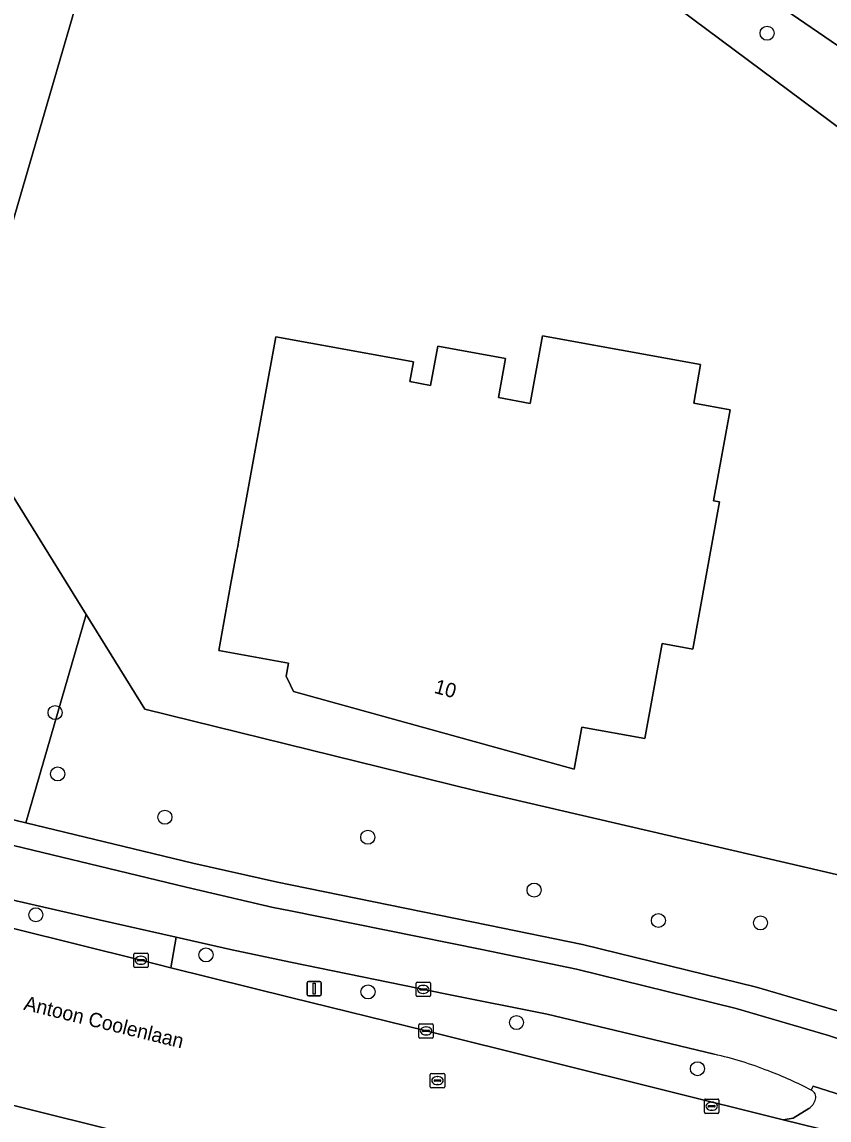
# Model space of a CAD drawing. Extents: x 159817 to 160765, y 380688 to 381638.
# Drawn here: x 160481.3 to 160537.5, y 380889.1 to 380965.5 of the extents above; entities that cross this region are included whole.
import ezdxf

# ---------------------------------------------------------------- set-up
doc = ezdxf.new("R2010")
doc.units = 0
for name, color, linetype in [('IMGEO_Berm_groen', 7, 'Continuous'), ('IMGEO_Boom', 7, 'Continuous'), ('IMGEO_Erf', 7, 'Continuous'), ('IMGEO_Fietspad_gesloten', 7, 'Continuous'), ('IMGEO_Gemengd_bos', 7, 'Continuous'), ('IMGEO_Grasland_overig', 7, 'Continuous'), ('IMGEO_Hek', 7, 'Continuous'), ('IMGEO_Kolk', 7, 'Continuous'), ('IMGEO_Lichtmast', 7, 'Continuous'), ('IMGEO_Openbare_ruimte_label', 7, 'Continuous'), ('IMGEO_Pand', 7, 'Continuous'), ('IMGEO_Pand_nummerreeks', 7, 'Continuous'), ('IMGEO_Rijbaan_lokaal_gesloten', 7, 'Continuous'), ('IMGEO_Rijbaan_lokaal_open', 7, 'Continuous'), ('IMGEO_Rioolput', 7, 'Continuous'), ('IMGEO_Verkeerseiland_gesloten', 7, 'Continuous'), ('IMGEO_Voetpad_gesloten', 7, 'Continuous'), ('IMGEO_Voetpad_open', 7, 'Continuous')]:
    doc.layers.add(name, color=color, linetype=linetype)

msp = doc.modelspace()

# ---------------------------------------------------------------- linework, layer by layer
at = {"layer": 'IMGEO_Berm_groen'}
for points in [[(160467.63, 380905.686), (160489.586, 380900.228), (160491.667, 380899.712), (160492.052, 380901.84), (160486.675, 380903.051), (160480.593, 380904.443)], [(160517.859, 380896.483), (160510.889, 380897.864), (160500, 380900.104), (160495.835, 380900.988), (160492.052, 380901.84), (160491.667, 380899.712), (160500, 380897.648), (160509.439, 380895.309), (160534.288, 380889.115), (160535.003, 380889.239), (160536.093, 380889.922)], [(160529.491, 380893.685), (160524.664, 380894.858), (160517.859, 380896.483)]]:
    msp.add_lwpolyline(points, dxfattribs=at)
for centre, radius, start, end in [((160524.069, 380869.182), 25.096, 68.45926, 77.52225), ((160524.458, 380869.13), 25.004, 61.86676, 69.33272), ((160535.56, 380890.771), 1.003, 302.13777, 347.91431), ((160536.055, 380890.71), 0.508, 342.8831, 67.62608)]:
    msp.add_arc(centre, radius, start, end, dxfattribs=at)
at = {"layer": 'IMGEO_Boom'}
for centre in [(160533.174, 380964.739), (160483.613, 380917.461), (160483.791, 380913.193), (160491.255, 380910.183), (160505.382, 380908.787), (160516.958, 380905.114), (160482.272, 380903.392), (160525.609, 380902.995), (160532.72, 380902.83), (160494.117, 380900.6), (160505.397, 380898.025), (160515.733, 380895.892), (160528.327, 380892.683)]:
    msp.add_circle(centre, 0.489, dxfattribs=at)
at = {"layer": 'IMGEO_Erf'}
for points in [[(160554.891, 380940.824), (160556.535, 380944.511), (160525.173, 380967.859), (160500, 380984.04), (160491.657, 380989.31), (160476.872, 380938.65), (160485.779, 380924.29), (160489.858, 380917.713), (160512.835, 380912.045), (160539.32, 380905.895)], [(160528.013, 380921.887), (160525.869, 380922.277), (160524.668, 380915.656), (160520.27, 380916.455), (160519.738, 380913.523), (160500.219, 380918.926), (160500, 380919.377), (160499.697, 380920.002), (160499.86, 380920.9), (160495.008, 380921.78), (160495.834, 380926.33), (160496.287, 380928.83), (160496.324, 380929.032), (160496.407, 380929.49), (160498.97, 380943.612), (160503.859, 380942.726), (160508.553, 380941.875), (160508.304, 380940.498), (160509.751, 380940.236), (160510.246, 380942.962), (160514.969, 380942.105), (160514.475, 380939.38), (160516.689, 380938.979), (160517.541, 380943.673), (160528.552, 380941.675), (160528.067, 380938.999), (160530.596, 380938.541), (160529.447, 380932.205), (160529.871, 380932.129)]]:
    msp.add_lwpolyline(points, close=True, dxfattribs=at)
at = {"layer": 'IMGEO_Fietspad_gesloten'}
for points in [[(160536.248, 380891.18), (160536.375, 380891.457), (160544.557, 380888.869), (160544.527, 380888.723), (160552.941, 380885.966), (160561.203, 380883.508), (160561.818, 380886.616), (160554.106, 380889.112), (160545.645, 380892.233), (160537.445, 380895.002), (160531.026, 380896.883), (160519.907, 380899.598), (160513.32, 380900.979), (160500, 380903.659), (160498.8, 380903.9), (160492.748, 380905.309), (160477.319, 380909.032)], [(160480.593, 380904.443), (160486.675, 380903.051), (160492.052, 380901.84), (160495.835, 380900.988), (160500, 380900.104), (160510.889, 380897.864), (160517.859, 380896.483), (160524.664, 380894.858), (160529.491, 380893.685)]]:
    msp.add_lwpolyline(points, dxfattribs=at)
for centre, radius, start, end in [((160524.069, 380869.182), 25.096, 68.45926, 77.52225), ((160524.458, 380869.13), 25.004, 61.86676, 69.33272)]:
    msp.add_arc(centre, radius, start, end, dxfattribs=at)
at = {"layer": 'IMGEO_Gemengd_bos'}
msp.add_lwpolyline([(160539.831, 380896.2), (160540.108, 380896.514), (160540.984, 380898.156), (160557.835, 380935.388), (160554.891, 380940.824), (160539.32, 380905.895), (160512.835, 380912.045), (160489.858, 380917.713), (160485.779, 380924.29), (160481.57, 380909.795), (160493.198, 380906.995), (160499.107, 380905.656), (160500, 380905.475), (160513.769, 380902.676), (160520.329, 380901.329), (160532.432, 380898.347), (160538.045, 380896.715)], close=True, dxfattribs=at)
at = {"layer": 'IMGEO_Grasland_overig'}
msp.add_lwpolyline([(160478.101, 380910.63), (160481.57, 380909.795), (160485.779, 380924.29), (160476.872, 380938.65), (160491.657, 380989.31), (160500, 380984.04), (160525.173, 380967.859), (160556.535, 380944.511), (160561.532, 380943.561), (160561.912, 380944.396), (160561.993, 380946.299), (160540.854, 380961.981), (160520.7, 380975.774), (160502.884, 380986.789), (160500, 380988.692), (160490.438, 380995.257), (160488.426, 380996.62), (160472.756, 380942.35), (160467.097, 380923.083), (160465.836, 380918.789)], dxfattribs=at)
at = {"layer": 'IMGEO_Hek'}
for points in [[(160556.535, 380944.511), (160525.173, 380967.859), (160500, 380984.04), (160491.657, 380989.31), (160476.872, 380938.65), (160485.779, 380924.29)], [(160485.779, 380924.29), (160489.858, 380917.713), (160512.835, 380912.045), (160539.32, 380905.895)]]:
    msp.add_lwpolyline(points, dxfattribs=at)
at = {"layer": 'IMGEO_Kolk'}
for p, q in [((160489.085, 380899.803), (160489.085, 380900.655)), ((160489.16, 380900.729), (160490.012, 380900.729)), ((160489.573, 380900.509), (160489.598, 380900.509)), ((160490.086, 380900.655), (160490.086, 380899.803)), ((160490.012, 380899.729), (160489.16, 380899.729)), ((160489.344, 380900.223), (160489.344, 380900.235)), ((160489.782, 380900.186), (160489.384, 380900.186)), ((160489.387, 380900.272), (160489.785, 380900.272)), ((160489.596, 380899.949), (160489.571, 380899.949)), ((160489.828, 380900.235), (160489.828, 380900.223)), ((160508.743, 380897.776), (160508.743, 380898.628)), ((160508.818, 380898.702), (160509.67, 380898.702)), ((160509.002, 380898.196), (160509.002, 380898.208)), ((160509.44, 380898.159), (160509.042, 380898.159)), ((160509.045, 380898.245), (160509.443, 380898.245)), ((160509.231, 380898.482), (160509.256, 380898.482)), ((160509.486, 380898.208), (160509.486, 380898.196)), ((160509.744, 380898.628), (160509.744, 380897.776)), ((160509.67, 380897.702), (160508.818, 380897.702)), ((160509.254, 380897.922), (160509.229, 380897.922)), ((160509.013, 380895.81), (160509.865, 380895.81)), ((160508.938, 380894.884), (160508.938, 380895.736)), ((160509.197, 380895.304), (160509.197, 380895.316)), ((160509.635, 380895.267), (160509.237, 380895.267)), ((160509.24, 380895.353), (160509.638, 380895.353)), ((160509.426, 380895.59), (160509.451, 380895.59)), ((160509.681, 380895.316), (160509.681, 380895.304)), ((160509.939, 380895.736), (160509.939, 380894.884)), ((160509.865, 380894.81), (160509.013, 380894.81)), ((160509.449, 380895.03), (160509.424, 380895.03)), ((160528.823, 380889.647), (160528.823, 380890.499)), ((160528.898, 380890.573), (160529.75, 380890.573)), ((160529.824, 380890.499), (160529.824, 380889.647)), ((160529.082, 380890.067), (160529.082, 380890.079)), ((160529.52, 380890.03), (160529.122, 380890.03)), ((160529.125, 380890.116), (160529.523, 380890.116)), ((160529.334, 380889.793), (160529.309, 380889.793)), ((160529.311, 380890.353), (160529.336, 380890.353)), ((160529.566, 380890.079), (160529.566, 380890.067)), ((160529.75, 380889.573), (160528.898, 380889.573))]:
    msp.add_line(p, q, dxfattribs=at)
for points in [[(160489.085, 380899.803), (160489.085, 380900.655)], [(160489.16, 380900.729), (160490.012, 380900.729)], [(160490.086, 380900.655), (160490.086, 380899.803)], [(160490.012, 380899.729), (160489.16, 380899.729)], [(160508.743, 380897.776), (160508.743, 380898.628)], [(160508.818, 380898.702), (160509.67, 380898.702)], [(160509.744, 380898.628), (160509.744, 380897.776)], [(160509.67, 380897.702), (160508.818, 380897.702)], [(160509.013, 380895.81), (160509.865, 380895.81)], [(160508.938, 380894.884), (160508.938, 380895.736)], [(160509.939, 380895.736), (160509.939, 380894.884)], [(160509.865, 380894.81), (160509.013, 380894.81)], [(160528.823, 380889.647), (160528.823, 380890.499)], [(160528.898, 380890.573), (160529.75, 380890.573)], [(160529.824, 380890.499), (160529.824, 380889.647)], [(160529.75, 380889.573), (160528.898, 380889.573)]]:
    msp.add_lwpolyline(points, dxfattribs=at)
for centre, radius, start, end in [((160489.162, 380900.653), 0.0765, 91.55205, 178.44795), ((160489.162, 380900.653), 0.0765, 91.55205, 178.44795), ((160490.01, 380900.653), 0.0765, 1.55205, 88.44795), ((160490.01, 380900.653), 0.0765, 1.55205, 88.44795), ((160489.162, 380899.805), 0.0765, 181.55205, 268.44795), ((160489.162, 380899.805), 0.0765, 181.55205, 268.44795), ((160489.384, 380900.232), 0.0403, 85.87752, 175.75265), ((160489.381, 380900.222), 0.0366, 178.93798, 274.71019), ((160489.785, 380900.229), 0.043, 264.86636, 352.45326), ((160489.789, 380900.234), 0.0386, 1.73085, 96.63898), ((160490.01, 380899.805), 0.0765, 271.55205, 358.44795), ((160490.01, 380899.805), 0.0765, 271.55205, 358.44795), ((160508.82, 380898.626), 0.0765, 91.55205, 178.44795), ((160508.82, 380898.626), 0.0765, 91.55205, 178.44795), ((160509.042, 380898.205), 0.0403, 85.87752, 175.75265), ((160509.039, 380898.195), 0.0366, 178.93798, 274.71019), ((160509.443, 380898.202), 0.043, 264.86636, 352.45326), ((160509.447, 380898.207), 0.0386, 1.73085, 96.63898), ((160509.668, 380898.626), 0.0765, 1.55205, 88.44795), ((160509.668, 380898.626), 0.0765, 1.55205, 88.44795), ((160508.82, 380897.778), 0.0765, 181.55205, 268.44795), ((160508.82, 380897.778), 0.0765, 181.55205, 268.44795), ((160509.668, 380897.778), 0.0765, 271.55205, 358.44795), ((160509.668, 380897.778), 0.0765, 271.55205, 358.44795), ((160509.015, 380895.734), 0.0765, 91.55205, 178.44795), ((160509.015, 380895.734), 0.0765, 91.55205, 178.44795), ((160509.863, 380895.734), 0.0765, 1.55205, 88.44795), ((160509.863, 380895.734), 0.0765, 1.55205, 88.44795), ((160509.237, 380895.313), 0.0403, 85.87752, 175.75265), ((160509.234, 380895.303), 0.0366, 178.93798, 274.71019), ((160509.638, 380895.31), 0.043, 264.86636, 352.45326), ((160509.642, 380895.315), 0.0386, 1.73085, 96.63898), ((160509.015, 380894.886), 0.0765, 181.55205, 268.44795), ((160509.015, 380894.886), 0.0765, 181.55205, 268.44795), ((160509.863, 380894.886), 0.0765, 271.55205, 358.44795), ((160509.863, 380894.886), 0.0765, 271.55205, 358.44795), ((160528.9, 380890.497), 0.0765, 91.55205, 178.44795), ((160528.9, 380890.497), 0.0765, 91.55205, 178.44795), ((160529.748, 380890.497), 0.0765, 1.55205, 88.44795), ((160529.748, 380890.497), 0.0765, 1.55205, 88.44795), ((160529.122, 380890.076), 0.0403, 85.87752, 175.75265), ((160529.119, 380890.066), 0.0366, 178.93798, 274.71019), ((160529.523, 380890.073), 0.043, 264.86636, 352.45326), ((160529.527, 380890.078), 0.0386, 1.73085, 96.63898), ((160528.9, 380889.649), 0.0765, 181.55205, 268.44795), ((160528.9, 380889.649), 0.0765, 181.55205, 268.44795), ((160529.748, 380889.649), 0.0765, 271.55205, 358.44795), ((160529.748, 380889.649), 0.0765, 271.55205, 358.44795)]:
    msp.add_arc(centre, radius, start, end, dxfattribs=at)
for centre, major_axis, ratio, start_param, end_param in [((160489.572, 380900.229), (-0.387, 0.002), 0.722429, 4.712389, 7.853982), ((160489.597, 380900.229), (-0.39, 0.002), 0.717154, 1.570796, 4.712389), ((160509.23, 380898.202), (-0.387, 0.002), 0.722429, 4.712389, 7.853982), ((160509.255, 380898.202), (-0.39, 0.002), 0.717154, 1.570796, 4.712389), ((160509.425, 380895.31), (-0.387, 0.002), 0.722429, 4.712389, 7.853982), ((160509.45, 380895.31), (-0.39, 0.002), 0.717154, 1.570796, 4.712389), ((160529.31, 380890.073), (-0.387, 0.002), 0.722429, 4.712389, 7.853982), ((160529.335, 380890.073), (-0.39, 0.002), 0.717154, 1.570796, 4.712389)]:
    msp.add_ellipse(centre, major_axis=major_axis, ratio=ratio, start_param=start_param, end_param=end_param, dxfattribs=at)
at = {"layer": 'IMGEO_Lichtmast'}
for p, q in [((160501.15, 380897.85), (160501.15, 380898.65)), ((160501.15, 380898.65), (160501.15, 380897.85)), ((160501.25, 380898.75), (160502.04, 380898.75)), ((160502.04, 380898.75), (160501.25, 380898.75)), ((160502.14, 380898.65), (160502.14, 380897.85)), ((160502.14, 380897.85), (160502.14, 380898.65)), ((160502.04, 380897.75), (160501.25, 380897.75)), ((160501.25, 380897.75), (160502.04, 380897.75))]:
    msp.add_line(p, q, dxfattribs=at)
msp.add_lwpolyline([(160501.57, 380898.625), (160501.72, 380898.625), (160501.72, 380897.875), (160501.57, 380897.875), (160501.57, 380898.625)], dxfattribs=at)
for centre, start, end in [((160501.25, 380898.65), 90, 180), ((160501.25, 380898.65), 90, 180), ((160502.04, 380898.65), 0, 90), ((160502.04, 380898.65), 360, 90), ((160501.25, 380897.85), 180, 270), ((160501.25, 380897.85), 180, 270), ((160502.04, 380897.85), 270, 0), ((160502.04, 380897.85), 270, 0)]:
    msp.add_arc(centre, 0.1, start, end, dxfattribs=at)
at = {"layer": 'IMGEO_Pand'}
msp.add_lwpolyline([(160529.871, 380932.129), (160529.447, 380932.205), (160530.596, 380938.541), (160528.067, 380938.999), (160528.552, 380941.675), (160517.541, 380943.673), (160516.689, 380938.979), (160514.475, 380939.38), (160514.969, 380942.105), (160510.246, 380942.962), (160509.751, 380940.236), (160508.304, 380940.498), (160508.553, 380941.875), (160503.859, 380942.726), (160498.97, 380943.612), (160496.407, 380929.49), (160496.324, 380929.032), (160496.287, 380928.83), (160495.834, 380926.33), (160495.008, 380921.78), (160499.86, 380920.9), (160499.697, 380920.002), (160500, 380919.377), (160500.219, 380918.926), (160519.738, 380913.523), (160520.27, 380916.455), (160524.668, 380915.656), (160525.869, 380922.277), (160528.013, 380921.887)], close=True, dxfattribs=at)
at = {"layer": 'IMGEO_Rijbaan_lokaal_gesloten'}
msp.add_lwpolyline([(160547.365, 380885.947), (160545.183, 380886.453), (160534.288, 380889.115), (160509.439, 380895.309), (160500, 380897.648), (160491.667, 380899.712), (160489.586, 380900.228), (160467.63, 380905.686), (160464.492, 380894.136), (160466.057, 380893.772), (160486.788, 380888.609), (160500, 380885.349), (160517.131, 380881.121)], dxfattribs=at)
at = {"layer": 'IMGEO_Rijbaan_lokaal_open'}
for points in [[(160536.375, 380891.457), (160536.248, 380891.18)], [(160544.158, 380888.844), (160544.527, 380888.723), (160544.557, 380888.869), (160536.375, 380891.457)], [(160536.093, 380889.922), (160535.003, 380889.239), (160534.288, 380889.115), (160545.183, 380886.453)]]:
    msp.add_lwpolyline(points, dxfattribs=at)
for centre, radius, start, end in [((160535.56, 380890.771), 1.003, 302.13777, 347.91431), ((160536.055, 380890.71), 0.508, 342.8831, 67.62608)]:
    msp.add_arc(centre, radius, start, end, dxfattribs=at)
at = {"layer": 'IMGEO_Rioolput'}
for p, q in [((160509.734, 380891.431), (160509.734, 380892.283)), ((160509.809, 380892.357), (160510.661, 380892.357)), ((160510.222, 380892.137), (160510.247, 380892.137)), ((160510.735, 380892.283), (160510.735, 380891.431)), ((160510.661, 380891.357), (160509.809, 380891.357)), ((160509.993, 380891.851), (160509.993, 380891.863)), ((160510.431, 380891.814), (160510.033, 380891.814)), ((160510.036, 380891.9), (160510.434, 380891.9)), ((160510.245, 380891.577), (160510.22, 380891.577)), ((160510.477, 380891.863), (160510.477, 380891.851))]:
    msp.add_line(p, q, dxfattribs=at)
for points in [[(160509.734, 380891.431), (160509.734, 380892.283)], [(160509.809, 380892.357), (160510.661, 380892.357)], [(160510.735, 380892.283), (160510.735, 380891.431)], [(160510.661, 380891.357), (160509.809, 380891.357)]]:
    msp.add_lwpolyline(points, dxfattribs=at)
for centre, radius, start, end in [((160509.811, 380892.281), 0.0765, 91.55205, 178.44795), ((160509.811, 380892.281), 0.0765, 91.55205, 178.44795), ((160510.659, 380892.281), 0.0765, 1.55205, 88.44795), ((160510.659, 380892.281), 0.0765, 1.55205, 88.44795), ((160509.811, 380891.433), 0.0765, 181.55205, 268.44795), ((160509.811, 380891.433), 0.0765, 181.55205, 268.44795), ((160510.033, 380891.86), 0.0403, 85.87752, 175.75265), ((160510.03, 380891.85), 0.0366, 178.93798, 274.71019), ((160510.434, 380891.857), 0.043, 264.86636, 352.45326), ((160510.438, 380891.862), 0.0386, 1.73085, 96.63898), ((160510.659, 380891.433), 0.0765, 271.55205, 358.44795), ((160510.659, 380891.433), 0.0765, 271.55205, 358.44795)]:
    msp.add_arc(centre, radius, start, end, dxfattribs=at)
for centre, major_axis, ratio, start_param, end_param in [((160510.221, 380891.857), (-0.387, 0.002), 0.722429, 4.712389, 7.853982), ((160510.246, 380891.857), (-0.39, 0.002), 0.717154, 1.570796, 4.712389)]:
    msp.add_ellipse(centre, major_axis=major_axis, ratio=ratio, start_param=start_param, end_param=end_param, dxfattribs=at)
at = {"layer": 'IMGEO_Verkeerseiland_gesloten'}
msp.add_lwpolyline([(160517.131, 380881.121), (160500, 380885.349), (160486.788, 380888.609), (160466.057, 380893.772), (160464.492, 380894.136)], dxfattribs=at)
at = {"layer": 'IMGEO_Voetpad_gesloten'}
msp.add_lwpolyline([(160561.993, 380946.299), (160561.912, 380944.396), (160561.532, 380943.561), (160557.835, 380935.388), (160540.984, 380898.156), (160540.108, 380896.514), (160539.831, 380896.2), (160540.922, 380895.885), (160541.962, 380897.648), (160562.973, 380944.072), (160563.903, 380949.548), (160562.834, 380949.826), (160553.133, 380956.542), (160523.462, 380977.083), (160517.22, 380981.259), (160500, 380992.185), (160489.191, 380999.235), (160488.426, 380996.62), (160490.438, 380995.257), (160500, 380988.692), (160502.884, 380986.789), (160520.7, 380975.774), (160540.854, 380961.981)], close=True, dxfattribs=at)
at = {"layer": 'IMGEO_Voetpad_open'}
for points in [[(160538.045, 380896.715), (160532.432, 380898.347), (160520.329, 380901.329), (160513.769, 380902.676), (160500, 380905.475), (160499.107, 380905.656), (160493.198, 380906.995), (160481.57, 380909.795), (160478.101, 380910.63)], [(160477.319, 380909.032), (160492.748, 380905.309), (160498.8, 380903.9), (160500, 380903.659), (160513.32, 380900.979), (160519.907, 380899.598), (160531.026, 380896.883), (160537.445, 380895.002), (160545.645, 380892.233)]]:
    msp.add_lwpolyline(points, dxfattribs=at)

# ---------------------------------------------------------------- texts
at = {"layer": 'IMGEO_Openbare_ruimte_label'}
msp.add_text('Antoon Coolenlaan', height=1, rotation=346.22785, dxfattribs=at).set_placement((160481.372, 380896.798))
at = {"layer": 'IMGEO_Pand_nummerreeks'}
msp.add_text('10', height=1, rotation=344.53014, dxfattribs=at).set_placement((160509.944, 380918.847))

doc.saveas('drawing.dxf')
